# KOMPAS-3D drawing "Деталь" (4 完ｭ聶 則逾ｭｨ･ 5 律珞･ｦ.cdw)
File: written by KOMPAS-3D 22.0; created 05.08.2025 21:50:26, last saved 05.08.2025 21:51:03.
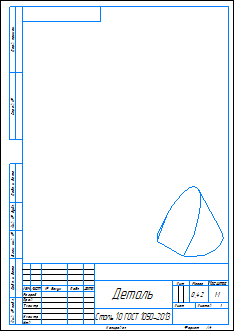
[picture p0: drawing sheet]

Sheet 1: A4, portrait

Document properties: Автор: user; Масса: 0.416415; Полное имя файла: G:\08 05 вторник\2025 НГ Лаб работы\Лаб 4 Сечение конуса\4 Чертежи\4 Конус Сечение 5 Чертеж.cdw

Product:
- Part/product: Деталь
    Масса: 0.416415

Title block, sheet 1: Наименование: Деталь; Материал: Сталь 10 ГОСТ 1050-2013; Масса: 0,42; Количество листов документа: 1; Форматы листов документа: A4; stored path: G:\08 05 вторник\2025 НГ Лаб работы\Лаб 4 Сечение конуса\4 Чертежи\4 Конус Сечение 7 Чертеж.cdw

Views: Изометрия 2
Dimensions and other numbers on the sheet: 1:1; 1; 0,42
